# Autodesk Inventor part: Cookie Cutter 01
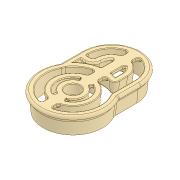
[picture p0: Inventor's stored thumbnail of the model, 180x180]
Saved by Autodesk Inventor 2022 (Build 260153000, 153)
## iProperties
RuleStatus: InUse
Created: 2022-09
Part Number: Cookie Cutter 01
Material: ABS Plastic
Document SubType Name: Modeling
Designer: Lance
Mass: 44.8406 g
Surface Area: 239.791 cm^2
Volume: 42.3024 cm^3
Density: 1.06 g/cm^3
Sheet Metal Rule: Default_mm
Appearance: Beige
BeforeDocSave0: MATERIAL DETAILS
BeforeDocSave1: ! iProps Material Part Number
BeforeDocSave2: CUSTOM iPROPS RULE
AfterDocNew0: IdentifyFiletype
AfterDocNew1: THICKNESS ENTRY
THICKNESS: 0.0
MASS: 0.0
ROLLING INSIDE RADIUS: 0.0
ROLLING OUTSIDE RADIUS: 0.0
OD: 0.0
ID: 0.0
ROLLINGLENGTH: 0.0
Author: Lance
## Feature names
1. Sweep1
2. Sweep2
3. Sweep3
4. Sweep4
5. Sweep9
6. Extrusion1
7. Extrusion2
8. Revolution1
9. Fillet1
10. Fillet3
11. Sweep5
12. Sweep6
13. Sweep7
14. Sweep8
15. Sweep11
16. Fillet4
17. Fillet5
18. Fillet6
19. Fillet7
20. Fillet10
21. Fillet9
22. TaggingFeature1
## Parameters: Thickness = 5 mm, BendRadius = 5 mm, BendReliefWidth = 5 mm, BendReliefDepth = 2.5 mm, SeamGap = 0.01 mm, TransitionRadius = 5 mm, JacobiRadiusSize = 5 mm, GapSize = 5 mm, Length = 0, Width = 0, Height = 0, Thick = 0, OD = 0, ID = 0, Wall = 0, Lip = 0, MassPerMetre = 0, FlatLength = 0, FlatWidth = 0, FlatThick = 0, FlatLong = 0, FlatShort = 0, ExtentsLong = 0, ExtentsMed = 0, ExtentsShort = 0, RollingOD = 0, RollingID = 0, RollingOutsideRadius = 0, RollingInsideRadius = 0, RollingWall = 0, RollingLength = 0, d1 = 0.5 mm, d2 = 10 deg, d3 = 6 mm, d4 = 0, d5 = 0, d6 = 0, d7 = 0, d8 = 0, d9 = 0, d10 = 0, d11 = 0, d12 = 0, d13 = 3 mm, d14 = 8 mm, d16 = 0, d18 = 0, d19 = 2 mm, d21 = 1 mm, d22 = 5.04964 mm, d23 = 1 mm, d24 = 1 mm, d25 = 0, d26 = 0, d27 = 0, d28 = 0, d29 = 0, d30 = 0, d31 = 2 mm, d32 = 0, d33 = 0, d34 = 3 mm, d35 = 0.5 mm, d36 = 0.5 mm, d37 = 0.5 mm, d38 = 3.5 mm, d39 = 2 mm, d40 = 90 deg, d43 = 0.5 mm, d44 = 2 mm, d45 = 0.5 mm, d46 = 5 mm, d47 = 0, d48 = 0, d51 = 0, d52 = 0, d53 = 6 mm
